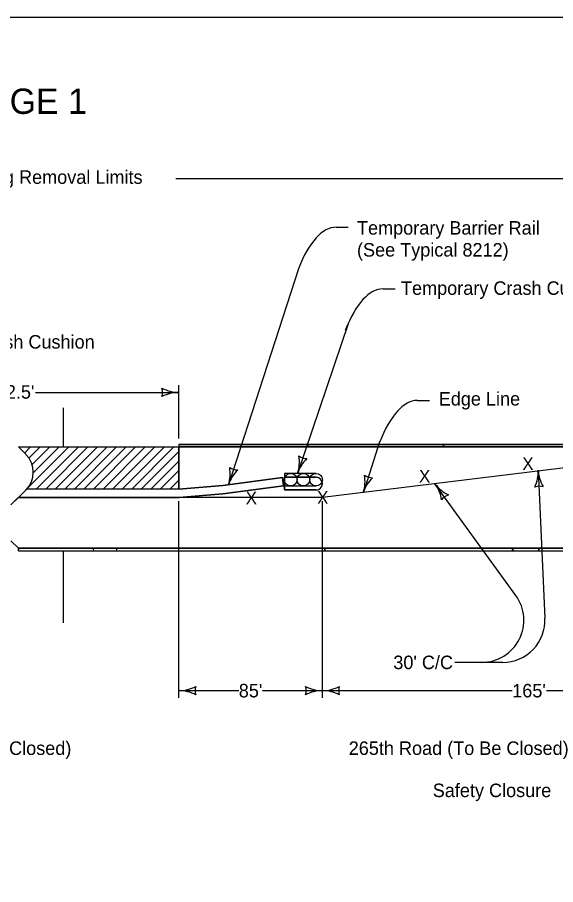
# Model space of a CAD drawing. Extents: x -2134934 to -2119606, y -2139046 to -2137036.
# Drawn here: x -2133366 to -2132728, y -2138064 to -2137036 of the extents above; entities that cross this region are included whole.
import ezdxf

# ---------------------------------------------------------------- set-up
doc = ezdxf.new("R2010")
doc.units = 0
for name, color, linetype in [('Default', 7, 'Continuous'), ('dsnCellElements', 7, 'Continuous'), ('dsnStdLabel', 7, 'Continuous'), ('dsnStdLineWork', 7, 'Continuous'), ('dsnStdShading', 7, 'Continuous'), ('Level 2', 7, 'Continuous')]:
    doc.layers.add(name, color=color, linetype=linetype)

msp = doc.modelspace()

# ---------------------------------------------------------------- linework, layer by layer
at = {"layer": 'Default'}
msp.add_lwpolyline([(-2134934.4, -2137035.9), (-2131799.4, -2137035.9), (-2131799.4, -2139045.9), (-2134934.4, -2139045.9)], close=True, dxfattribs=at)
at = {"layer": 'dsnCellElements'}
for centre, radius, start, end in [((-2133074.2, -2137563.4), 42.5, 342.0849, 10.1574), ((-2132993.3, -2137589.6), 42.5, 134.0124, 162.0849), ((-2133022.8, -2137542.6), 16.4, 234.3516, 269.8183), ((-2133156.1, -2137576.9), 42.5, 342.0849, 10.1574), ((-2133075.2, -2137603.1), 42.5, 134.0124, 162.0849), ((-2133104.7, -2137556.1), 16.4, 234.3516, 269.8183), ((-2132791.4, -2137574.5), 42.5, 334.5429, 2.6154), ((-2132706.5, -2137570.6), 42.5, 182.6154, 210.6879), ((-2132996.5, -2137586.2), 42.5, 342.0849, 10.1574), ((-2132915.6, -2137612.3), 42.5, 134.0124, 162.0849), ((-2132945.1, -2137565.3), 16.4, 234.3516, 269.8183), ((-2132836.9, -2137563.7), 42.5, 216.299, 244.3715), ((-2132905.4, -2137614), 42.5, 8.2265, 36.299), ((-2132747.3, -2137608.2), 16.4, 74.8821, 110.3488), ((-2132850.1, -2137617.6), 16.4, 108.5657, 144.0324), ((-2133174.4, -2137791.6), 42.5, 270, 298.0725), ((-2133138.8, -2137834.1), 16.4, 162.2666, 197.7334), ((-2133040, -2137834.1), 16.4, 342.2666, 17.7333), ((-2133004.4, -2137791.6), 42.5, 241.9275, 270), ((-2133004.4, -2137791.6), 42.5, 270, 298.0725), ((-2132968.8, -2137834.1), 16.4, 162.2666, 197.7334), ((-2133174.4, -2137876.6), 42.5, 61.9275, 90), ((-2133004.4, -2137876.6), 42.5, 90, 118.0725), ((-2133004.4, -2137876.6), 42.5, 61.9275, 90)]:
    msp.add_arc(centre, radius, start, end, dxfattribs=at)
at = {"layer": 'dsnStdLineWork'}
for p, q in [((-2133174.4, -2137542.2), (-2133174.4, -2137545.2)), ((-2133174.4, -2137542.2), (-2133174.4, -2137545.2)), ((-2133100.2, -2137542.2), (-2133174.4, -2137542.2)), ((-2133100.2, -2137542.2), (-2133101.2, -2137545.2)), ((-2133101.2, -2137545.2), (-2133100.2, -2137542.2)), ((-2133021.1, -2137542.2), (-2133100.2, -2137542.2)), ((-2133021.1, -2137542.2), (-2133022.1, -2137545.2)), ((-2133022.1, -2137545.2), (-2133021.1, -2137542.2)), ((-2132860.7, -2137542.2), (-2133021.1, -2137542.2)), ((-2132860.7, -2137542.2), (-2132861.6, -2137545.2)), ((-2132861.6, -2137545.2), (-2132860.7, -2137542.2)), ((-2132547, -2137542.2), (-2132860.7, -2137542.2)), ((-2133174.4, -2137545.2), (-2133173.7, -2137545.2)), ((-2133173.7, -2137545.2), (-2133101.2, -2137545.2)), ((-2133101.2, -2137545.2), (-2133022.1, -2137545.2)), ((-2133022.1, -2137545.2), (-2132861.6, -2137545.2)), ((-2132861.6, -2137545.2), (-2132568.7, -2137545.2)), ((-2133364.4, -2137668.2), (-2133364.4, -2137665.2)), ((-2133364.4, -2137665.2), (-2131862, -2137665.2)), ((-2133364.4, -2137665.2), (-2131862, -2137665.2)), ((-2133276.3, -2137665.2), (-2133364.4, -2137665.2)), ((-2133364.4, -2137665.2), (-2133364.4, -2137668.2)), ((-2133247.5, -2137665.2), (-2133276.3, -2137665.2)), ((-2133001.5, -2137665.2), (-2133247.5, -2137665.2)), ((-2133001.5, -2137668.2), (-2133001.5, -2137665.2)), ((-2132780.1, -2137665.2), (-2133001.5, -2137665.2)), ((-2133001.5, -2137665.2), (-2133001.5, -2137668.2)), ((-2132778, -2137668.2), (-2132780.1, -2137665.2)), ((-2132780.1, -2137665.2), (-2132778, -2137668.2)), ((-2132748.3, -2137665.2), (-2132780.1, -2137665.2)), ((-2132748.2, -2137668.2), (-2132748.3, -2137665.2)), ((-2132714.9, -2137665.2), (-2132748.3, -2137665.2)), ((-2132748.3, -2137665.2), (-2132748.2, -2137668.2)), ((-2133364.4, -2137668.2), (-2131862, -2137668.2)), ((-2133364.4, -2137668.2), (-2133275.4, -2137668.2)), ((-2133275.4, -2137668.2), (-2133248.5, -2137668.2)), ((-2133248.5, -2137668.2), (-2133001.5, -2137668.2)), ((-2133001.5, -2137668.2), (-2132778, -2137668.2)), ((-2132778, -2137668.2), (-2132748.2, -2137668.2)), ((-2132748.2, -2137668.2), (-2132714.9, -2137668.2))]:
    msp.add_line(p, q, dxfattribs=at)
for points in [[(-2133174.4, -2137542.2), (-2131862, -2137542.2)], [(-2133174.4, -2137545.2), (-2131862, -2137545.2)], [(-2133173.7, -2137545.2), (-2131861.3, -2137545.2)]]:
    msp.add_lwpolyline(points, dxfattribs=at)
for start, end in [(191.3299, 203.618), (191.3299, 203.618), (336.382, 348.6701), (336.382, 348.6701)]:
    msp.add_arc((-2133261.9, -2137662.3), 14.7, start, end, dxfattribs=at)
at = {"layer": 'dsnStdShading'}
for p, q in [((-2133011.9, -2137581.2), (-2133049.4, -2137581.2)), ((-2133049.4, -2137581.2), (-2133049.4, -2137596.2)), ((-2133049.4, -2137596.2), (-2133011.9, -2137596.2))]:
    msp.add_line(p, q, dxfattribs=at)
msp.add_arc((-2133011.9, -2137588.7), 7.5, 270.0024, 89.9972, dxfattribs=at)
at = {"layer": 'Level 2'}
for p, q in [((-2133178, -2137227), (-2132514.4, -2137227)), ((-2132988.2, -2137284.8), (-2132973.9, -2137284.8)), ((-2133032.9, -2137333.9), (-2133115.7, -2137590)), ((-2132932.7, -2137357.9), (-2132918.5, -2137357.9)), ((-2132973.7, -2137398.2), (-2133033.8, -2137576.5)), ((-2133174.4, -2137535.2), (-2133174.4, -2137471.9)), ((-2133344, -2137480.5), (-2133174.4, -2137480.5)), ((-2132891.9, -2137490.1), (-2132877.7, -2137490.1)), ((-2133311.5, -2137498.8), (-2133311.5, -2137545.2)), ((-2132936.7, -2137539.2), (-2132956, -2137599.2)), ((-2133355.7, -2137553.9), (-2133364.4, -2137545.2)), ((-2133357.2, -2137552.4), (-2133350, -2137545.2)), ((-2133353.3, -2137593.7), (-2133304.8, -2137545.2)), ((-2133352, -2137558.4), (-2133338.7, -2137545.2)), ((-2133348.3, -2137566.1), (-2133327.4, -2137545.2)), ((-2133346.9, -2137576), (-2133316.1, -2137545.2)), ((-2133343.4, -2137595.2), (-2133293.4, -2137545.2)), ((-2133332.1, -2137595.2), (-2133282.1, -2137545.2)), ((-2133320.8, -2137595.2), (-2133270.8, -2137545.2)), ((-2133309.5, -2137595.2), (-2133259.5, -2137545.2)), ((-2133298.2, -2137595.2), (-2133248.2, -2137545.2)), ((-2133286.9, -2137595.2), (-2133236.9, -2137545.2)), ((-2133275.6, -2137595.2), (-2133225.6, -2137545.2)), ((-2133264.2, -2137595.2), (-2133214.2, -2137545.2)), ((-2133252.9, -2137595.2), (-2133202.9, -2137545.2)), ((-2133241.6, -2137595.2), (-2133191.6, -2137545.2)), ((-2133230.3, -2137595.2), (-2133180.3, -2137545.2)), ((-2133219, -2137595.2), (-2133174.4, -2137550.6)), ((-2133174.4, -2137595.2), (-2133174.4, -2137545.2)), ((-2131862, -2137545.2), (-2133174.4, -2137545.2)), ((-2133174.4, -2137545.2), (-2133174.4, -2137595.2)), ((-2132514.4, -2137545.2), (-2133004.4, -2137605.2)), ((-2133207.7, -2137595.2), (-2133174.4, -2137561.9)), ((-2133196.4, -2137595.2), (-2133174.4, -2137573.2)), ((-2132749, -2137572.6), (-2132740.9, -2137748.3)), ((-2133185.1, -2137595.2), (-2133174.4, -2137584.5)), ((-2133051.7, -2137581.6), (-2133122.2, -2137590.8)), ((-2133122.2, -2137590.8), (-2133051.7, -2137581.6)), ((-2133122.2, -2137590.8), (-2133051.7, -2137581.6)), ((-2133050.4, -2137591.5), (-2133051.7, -2137581.6)), ((-2133051.7, -2137581.6), (-2133050.4, -2137591.5)), ((-2133051.7, -2137581.6), (-2133050.4, -2137591.5)), ((-2133049.4, -2137576.5), (-2133049.4, -2137591.5)), ((-2133011.9, -2137576.5), (-2133049.4, -2137576.5)), ((-2133049.4, -2137596.2), (-2133049.4, -2137581.2)), ((-2133049.4, -2137581.2), (-2133011.9, -2137581.2)), ((-2133174.3, -2137595.2), (-2133354.4, -2137595.2)), ((-2133174.3, -2137595.2), (-2133354.4, -2137595.2)), ((-2133174.4, -2137595.2), (-2133122.2, -2137590.8)), ((-2133122.2, -2137590.8), (-2133174.3, -2137595.2)), ((-2133174.3, -2137595.2), (-2133122.2, -2137590.8)), ((-2133122.3, -2137600.8), (-2133050.4, -2137591.5)), ((-2133050.4, -2137591.5), (-2133122.3, -2137600.8)), ((-2133050.4, -2137591.5), (-2133122.3, -2137600.8)), ((-2133049.4, -2137591.5), (-2133011.9, -2137591.5)), ((-2132775.4, -2137721.3), (-2132871.2, -2137588.8)), ((-2133373.2, -2137613.9), (-2133355.7, -2137596.4)), ((-2133355.7, -2137596.4), (-2133364.4, -2137605.2)), ((-2133364.4, -2137605.2), (-2133173.9, -2137605.2)), ((-2133173.9, -2137605.2), (-2133364.4, -2137605.2)), ((-2133173.9, -2137605.2), (-2133364.4, -2137605.2)), ((-2133173.9, -2137605.2), (-2133122.3, -2137600.8)), ((-2133122.3, -2137600.8), (-2133173.9, -2137605.2)), ((-2133122.3, -2137600.8), (-2133173.9, -2137605.2)), ((-2133004.4, -2137605.2), (-2133173.9, -2137605.2)), ((-2133011.9, -2137596.2), (-2133049.4, -2137596.2)), ((-2133174.4, -2137842.8), (-2133174.4, -2137609.3)), ((-2133004.4, -2137842.8), (-2133004.4, -2137609.3)), ((-2133364.4, -2137665.2), (-2133373.2, -2137656.4)), ((-2133373.2, -2137656.4), (-2133364.4, -2137665.2)), ((-2133364.4, -2137665.2), (-2131862, -2137665.2)), ((-2133311.5, -2137668.2), (-2133311.5, -2137753.6)), ((-2132790.9, -2137800.6), (-2132847.6, -2137800.6)), ((-2133174.4, -2137834.1), (-2133103.5, -2137834.1)), ((-2133075.4, -2137834.1), (-2133004.4, -2137834.1)), ((-2133004.4, -2137834.1), (-2132779.7, -2137834.1)), ((-2132739.2, -2137834.1), (-2132514.4, -2137834.1))]:
    msp.add_line(p, q, dxfattribs=at)
for points in [[(-2133364.4, -2137545.2), (-2133174.4, -2137545.2)], [(-2133354.4, -2137595.2), (-2133354.5, -2137595.1)], [(-2133364.4, -2137605.2), (-2133364.4, -2137605.2), (-2133373.2, -2137613.9)]]:
    msp.add_lwpolyline(points, dxfattribs=at)
for centre in [(-2133041.9, -2137584), (-2133041.9, -2137584), (-2133026.9, -2137584), (-2133026.9, -2137584), (-2133011.9, -2137584), (-2133011.9, -2137584)]:
    msp.add_circle(centre, 7.5, dxfattribs=at)
for centre, radius, start, end in [((-2133210.1, -2137480.5), 16.4, 342.2666, 17.7333), ((-2133174.4, -2137438), 42.5, 241.9275, 270), ((-2133174.4, -2137523), 42.5, 90, 118.0725), ((-2133376.9, -2137575.2), 30, 315, 45), ((-2133011.9, -2137588.7), 7.5, 269.9996, 90), ((-2133376.9, -2137575.2), 30, 315, 318.2713), ((-2132815.9, -2137750.6), 50, 270, 35.862), ((-2132790.9, -2137750.6), 50, 270, 2.6154)]:
    msp.add_arc(centre, radius, start, end, dxfattribs=at)
for centre in [(-2132988.2, -2137497.7), (-2132932.7, -2137570.8), (-2132891.9, -2137703)]:
    msp.add_ellipse(centre, major_axis=(0, 212.9), ratio=0.328743, start_param=0, end_param=0.693162, dxfattribs=at)

# ---------------------------------------------------------------- texts
at = {"layer": 'dsnStdLabel'}
msp.add_text('STAGE 1', height=30, dxfattribs=at).set_placement((-2133452.8, -2137150.4))
at = {"layer": 'Level 2'}
for s, height, p in [('Pavement Marking Removal Limits', 16, (-2133548, -2137233.3)), ('Temporary Barrier Rail', 16, (-2132963.5, -2137293.5)), ('(See Typical 8212)', 16, (-2132963.5, -2137319.5)), ('Temporary Crash Cushion', 16, (-2132911.4, -2137364.9)), ('Temporary Crash Cushion', 16, (-2133525, -2137428.6)), ("392.5'", 16, (-2133403.1, -2137488)), ('Edge Line', 16, (-2132866.7, -2137496.1)), ('X', 15, (-2133095.3, -2137613.2)), ('X', 15, (-2133010.8, -2137612.6)), ("30' C/C", 16, (-2132920.5, -2137808.6)), ("85'", 16, (-2133103.5, -2137842.1)), ("165'", 16, (-2132779.7, -2137842.1)), ('Field Entrance (To Be Closed)', 16, (-2133589.5, -2137910.3)), ('265th Road (To Be Closed)', 16, (-2132973.3, -2137910.3)), ('Safety Closure', 16, (-2132873.8, -2137960.3))]:
    msp.add_text(s, height=height, dxfattribs=at).set_placement(p)
for p in [(-2132767.8, -2137572.6), (-2132890.1, -2137587.4)]:
    msp.add_text('X', height=15, rotation=359.9705, dxfattribs=at).set_placement(p)

doc.saveas('drawing.dxf')
